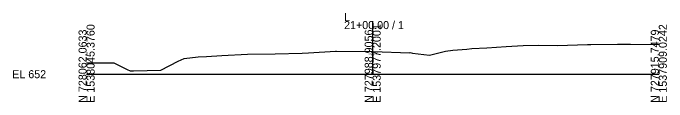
# Model space of a CAD drawing. Extents: x -26 to 1203, y -10 to 9522.
# Drawn here: x 974.3 to 1202.8, y 2490.3 to 2521.4 of the extents above; entities that cross this region are included whole.
import ezdxf

# ---------------------------------------------------------------- set-up
doc = ezdxf.new("R2010")
doc.units = 0
for name, color, linetype in [('Default', 7, 'Continuous'), ('Exist Cross Section Cell', 7, 'Continuous'), ('Exist XS Center Line Elevation Label', 7, 'Continuous'), ('Exist XS Ground Line', 7, 'Continuous')]:
    doc.layers.add(name, color=color, linetype=linetype)

msp = doc.modelspace()

# ---------------------------------------------------------------- linework, layer by layer
at = {"layer": 'Exist Cross Section Cell'}
for p, q in [((1100, 2500), (1100, 2518.57)), ((1000, 2500), (1100, 2500)), ((1100, 2500), (1200, 2500))]:
    msp.add_line(p, q, dxfattribs=at)
at = {"layer": 'Exist XS Ground Line'}
msp.add_lwpolyline([(1000, 2504), (1009.53, 2504.02), (1014.14, 2501.68), (1015.2, 2501.22), (1016.45, 2501.19), (1025.94, 2501.43), (1032.02, 2504.56), (1034.16, 2505.51), (1039.02, 2506.03), (1041.93, 2506.17), (1047.33, 2506.56), (1056.22, 2507.01), (1065.91, 2507.08), (1075.32, 2507.38), (1077.58, 2507.45), (1087.03, 2508.02), (1087.35, 2508.03), (1099.86, 2507.93), (1099.93, 2507.93), (1099.99, 2507.92), (1100, 2507.92), (1112.98, 2507.41), (1113.13, 2507.56), (1113.94, 2507.3), (1119.81, 2506.66), (1124.52, 2507.84), (1125.4, 2508.08), (1127.99, 2508.37), (1132.9, 2508.75), (1134.65, 2508.94), (1139.9, 2509.2), (1146.67, 2509.74), (1152.62, 2510), (1158.11, 2510.1), (1164.58, 2510.02), (1175.09, 2510.4), (1176.19, 2510.42), (1185.52, 2510.53), (1190.11, 2510.51), (1200, 2510.39)], dxfattribs=at)

# ---------------------------------------------------------------- texts
at = {"layer": 'Default'}
msp.add_text('-', height=0.0001, dxfattribs=at).set_placement((1000, 2500))
msp.add_text('-', height=0.0001, dxfattribs=at).set_placement((1000, 2500))
msp.add_text('-', height=0.0001, dxfattribs=at).set_placement((1000, 2500))
at = {"layer": 'Exist Cross Section Cell'}
for s, p in [('L', (1090, 2518.57)), ('21+00.00 / 1', (1090, 2515.77)), ('EL 652', (974, 2498.6))]:
    msp.add_text(s, height=2.8, dxfattribs=at).set_placement(p)
for s, p in [('E 1538045.3760', (1002.8, 2490)), ('E 1537977.2001', (1102.8, 2490)), ('E 1537909.0242', (1202.8, 2490)), ('N 728062.0633', (1000, 2490)), ('N 727988.9056', (1100, 2490)), ('N 727915.7479', (1200, 2490))]:
    msp.add_text(s, height=2.8, rotation=90, dxfattribs=at).set_placement(p)
at = {"layer": 'Exist XS Center Line Elevation Label'}
msp.add_text('659.92', height=0.75, dxfattribs=at).set_placement((1098.48, 2506.95))

doc.saveas('drawing.dxf')
